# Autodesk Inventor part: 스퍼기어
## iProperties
Created: 2013-08
Part Number: 스퍼기어
Material: Steel
Document SubType Name: Modeling
Designer: 한국산업디자인학원
Categories: <?xml version="1.0" encoding="UTF-16"?> <MemberInstance><Categories><FamilyTemplate><FamilyTemplateParameter ValueType="xs:double" Id="1" ObjectReferenceKey="da
Density: 1 g/cm^3
CustomPartVersion: 1
Author: 한국산업디자인학원
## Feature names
1. Extrusion1
